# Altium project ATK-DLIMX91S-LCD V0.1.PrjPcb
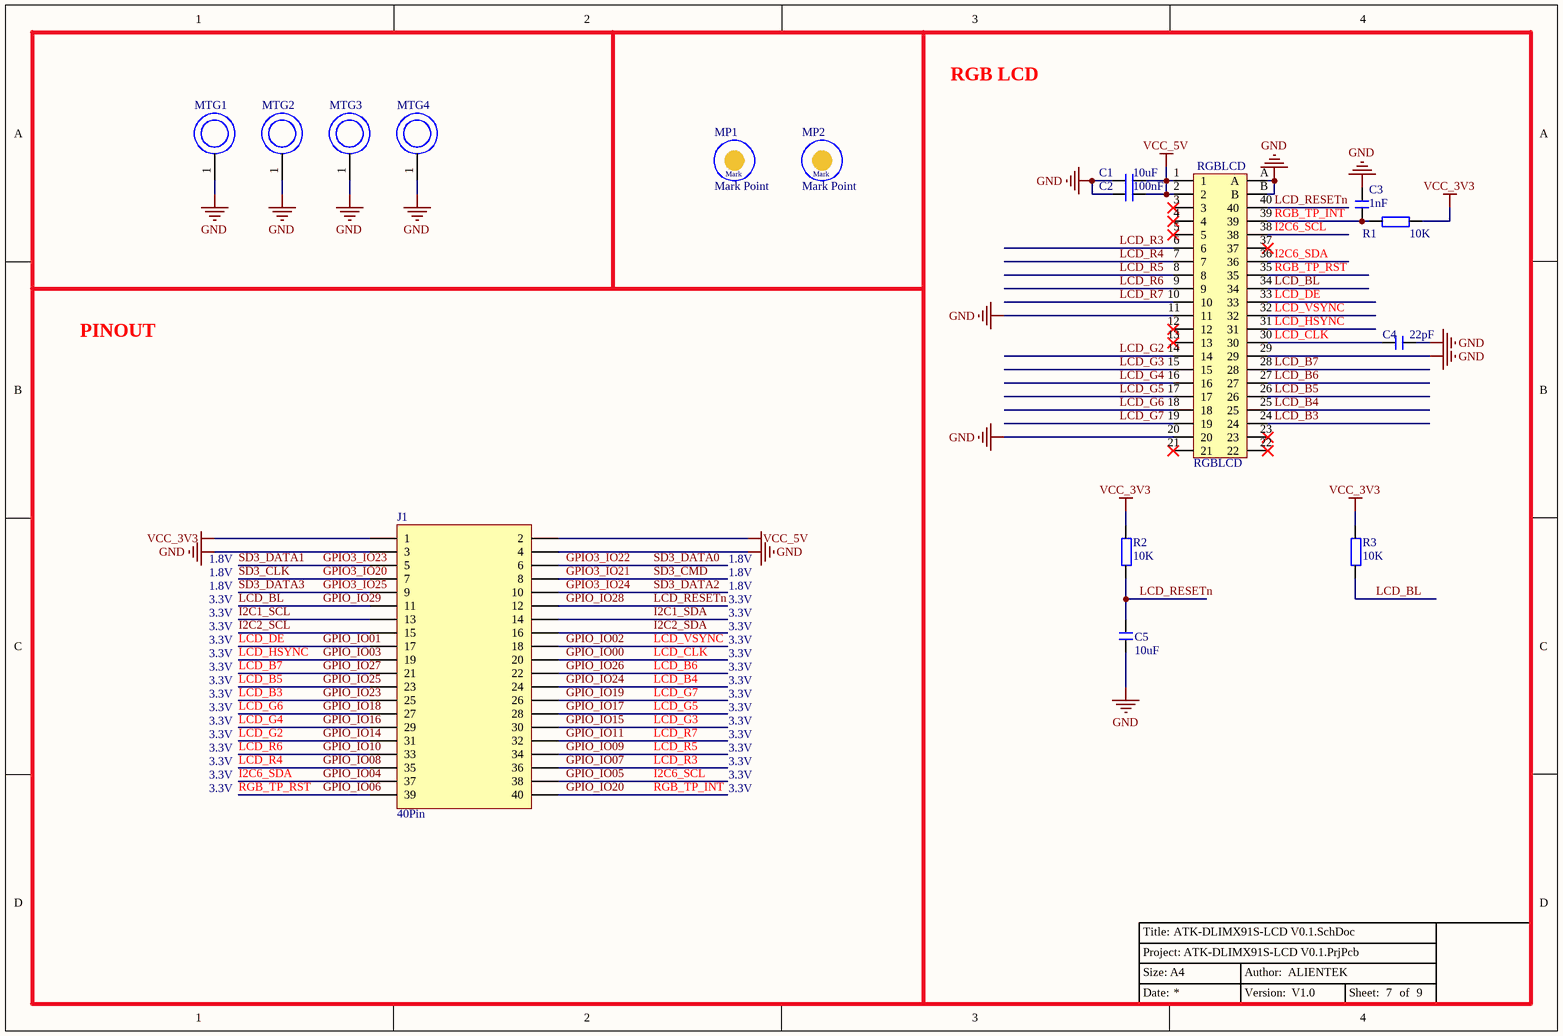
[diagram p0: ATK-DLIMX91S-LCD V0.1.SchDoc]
1 sheet, 16 parts. Net scope: global (net labels, ports and power ports of the same name join across sheets).
Board files: ATK-DLIMX91S-LCD V0.1.PcbDoc, ATK-DLIMX91XS-LCD V0.0.PcbDoc

## Sheet ATK-DLIMX91S-LCD V0.1.SchDoc
size A4; Author: ALIENTEK; Revision: 0; SheetNumber: 7; SheetTotal: 9; Version: V1.0; SheetSize: A4

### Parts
C1  10uF  [C 0603]
C2  100nF  [C 0603]
C3  1nF  [C 0603]
C4  22pF  [C 0603]
C5  10uF  [C 0603]
J1  40Pin  [HDR-20X2]
MP1  Mark Point  [MARK POINT]
MP2  Mark Point  [MARK POINT]
MTG1  MTG_Hole  [M3-6ET]  (value not drawn)
MTG2  MTG_Hole  [M3-6ET]  (value not drawn)
MTG3  MTG_Hole  [M3-6ET]  (value not drawn)
MTG4  MTG_Hole  [M3-6ET]  (value not drawn)
R1  10K  [R 0603]
R2  10K  [R 0603]
R3  10K  [R 0603]
RGBLCD  RGBLCD  [FPC0.5-TOP40P]

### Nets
GND: C1.2 C2.2 C3.1 C4.2 C5.2 J1.3 J1.4 MTG1.1 MTG2.1 MTG3.1 MTG4.1 RGBLCD.11 RGBLCD.20 RGBLCD.29 RGBLCD.A RGBLCD.B
VCC_3V3: J1.1 R1.2 R2.2 R3.2
VCC_5V: C1.1 C2.1 J1.2 RGBLCD.1 RGBLCD.2
GPIO3_IO20: J1.7  [also labelled SD3_CLK]
GPIO3_IO21: J1.8  [also labelled SD3_CMD]
GPIO3_IO22: J1.6  [also labelled SD3_DATA0]
GPIO3_IO23: J1.5  [also labelled SD3_DATA1]
GPIO3_IO24: J1.10  [also labelled SD3_DATA2]
GPIO3_IO25: J1.9  [also labelled SD3_DATA3]
GPIO_IO00: C4.1 J1.20 RGBLCD.30  [also labelled LCD_CLK]
GPIO_IO01: J1.17 RGBLCD.33  [also labelled LCD_DE]
GPIO_IO02: J1.18 RGBLCD.32  [also labelled LCD_VSYNC]
GPIO_IO03: J1.19 RGBLCD.31  [also labelled LCD_HSYNC]
GPIO_IO04: J1.37 RGBLCD.36  [also labelled I2C6_SDA]
GPIO_IO05: J1.38 RGBLCD.38  [also labelled I2C6_SCL]
GPIO_IO06: J1.39 RGBLCD.35  [also labelled RGB_TP_RST]
GPIO_IO07: J1.36 RGBLCD.6  [also labelled LCD_R3]
GPIO_IO08: J1.35 RGBLCD.7  [also labelled LCD_R4]
GPIO_IO09: J1.34 RGBLCD.8  [also labelled LCD_R5]
GPIO_IO10: J1.33 RGBLCD.9  [also labelled LCD_R6]
GPIO_IO11: J1.32 RGBLCD.10  [also labelled LCD_R7]
GPIO_IO14: J1.31 RGBLCD.14  [also labelled LCD_G2]
GPIO_IO15: J1.30 RGBLCD.15  [also labelled LCD_G3]
GPIO_IO16: J1.29 RGBLCD.16  [also labelled LCD_G4]
GPIO_IO17: J1.28 RGBLCD.17  [also labelled LCD_G5]
GPIO_IO18: J1.27 RGBLCD.18  [also labelled LCD_G6]
GPIO_IO19: J1.26 RGBLCD.19  [also labelled LCD_G7]
GPIO_IO20: C3.2 J1.40 R1.1 RGBLCD.39  [also labelled RGB_TP_INT]
GPIO_IO23: J1.25 RGBLCD.24  [also labelled LCD_B3]
GPIO_IO24: J1.24 RGBLCD.25  [also labelled LCD_B4]
GPIO_IO25: J1.23 RGBLCD.26  [also labelled LCD_B5]
GPIO_IO26: J1.22 RGBLCD.27  [also labelled LCD_B6]
GPIO_IO27: J1.21 RGBLCD.28  [also labelled LCD_B7]
GPIO_IO28: C5.1 J1.12 R2.1 RGBLCD.40  [also labelled LCD_RESETn]
GPIO_IO29: J1.11 R3.1 RGBLCD.34  [also labelled LCD_BL]
I2C1_SCL: J1.13
I2C1_SDA: J1.14
I2C2_SCL: J1.15
I2C2_SDA: J1.16

Not connected (* = marked no-connect by the designer): MP1 1; MP2 1; RGBLCD 3* 4* 5* 12* 13* 21* 22* 23* 37*

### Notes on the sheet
- RGB LCD
- PINOUT
- 1.8V
- 3.3V

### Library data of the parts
C1 C2 C5 = C: 无极性贴片电容; 版权归属: 源创客
C3 C4 = C: 无极性贴片电容; 版权归属: 正点原子
J1 = RPI40Pin
MP1 MP2 = MARK
MTG1-MTG4 = MTG_Hole: 螺丝孔
R1-R3 = R
RGBLCD = FPC-40: FPC-40P-0.5mm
